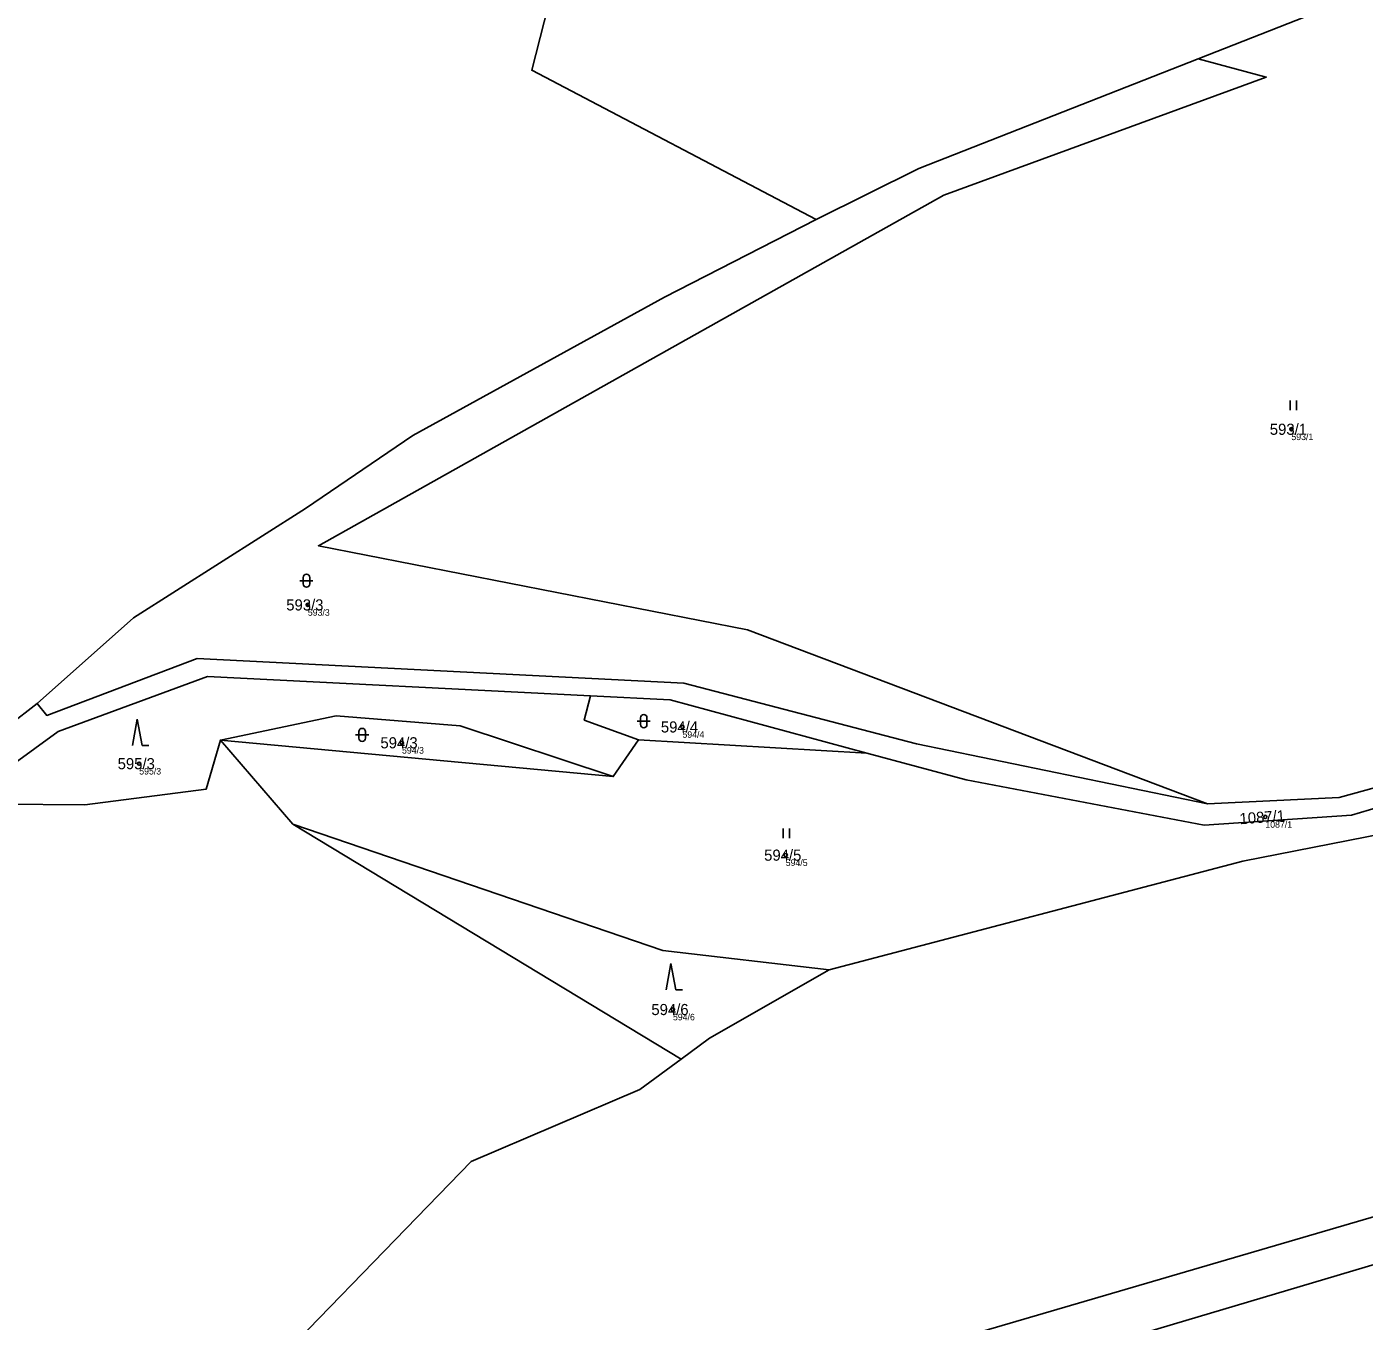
# Model space of a CAD drawing. Extents: x -554500 to -548272, y -1079733 to -1073730.
# Drawn here: x -553040.5 to -552836.2, y -1076175.5 to -1075977.7 of the extents above; entities that cross this region are included whole.
import ezdxf

# ---------------------------------------------------------------- set-up
doc = ezdxf.new("R2010")
doc.units = 0
for name, color, linetype in [('Definiční body', 7, 'Continuous'), ('Hranice parcel', 7, 'Continuous'), ('Parcelní čísla', 7, 'Continuous'), ('Polygon parcely', 7, 'Continuous'), ('Značky kultur', 7, 'Continuous')]:
    doc.layers.add(name, color=color, linetype=linetype)

msp = doc.modelspace()

# ---------------------------------------------------------------- linework, layer by layer
at = {"layer": 'Definiční body'}
for centre in [(-552847.3, -1076039.17994), (-552997.58, -1076066.01994), (-552940.34, -1076084.66994), (-552983.19, -1076087.08994), (-553023.34, -1076090.27994), (-552851.28, -1076098.41994), (-552924.56, -1076104.25994), (-552941.79, -1076127.84994)]:
    msp.add_circle(centre, 0.25, dxfattribs=at)
at = {"layer": 'Hranice parcel'}
for p, q in [((-552861.56, -1075982.55), (-552838.34, -1075973.42)), ((-553010.93, -1076086.68), (-552950.9, -1076092.26)), ((-552999.87, -1076099.51), (-553010.93, -1076086.68)), ((-552950.9, -1076092.26), (-552947.08, -1076086.65)), ((-552947.08, -1076086.65), (-552912.15, -1076088.67)), ((-552940.56, -1076135.41), (-552999.87, -1076099.51))]:
    msp.add_line(p, q, dxfattribs=at)
for points in [[(-552919.92, -1076007.14), (-552963.37, -1075984.31), (-552959.56, -1075969.5), (-552981.08, -1075928.96), (-552995.11, -1075875.98), (-552991.19, -1075866.06), (-552990.49, -1075854.9), (-553000.03, -1075843.3), (-553017.31, -1075831.78), (-553046.52, -1075836.31)], [(-552861.56, -1075982.55), (-552851.15, -1075985.37), (-552900.4, -1076003.39), (-552995.96, -1076056.98), (-552930.41, -1076069.82), (-552860.14, -1076096.43)], [(-552919.92, -1076007.14), (-552904.2, -1075999.32), (-552861.56, -1075982.55)], [(-553038.93, -1076081.06), (-553024.21, -1076067.98), (-552997.92, -1076051.27), (-552981.53, -1076040.12), (-552943.09, -1076018.97), (-552919.92, -1076007.14)], [(-552860.14, -1076096.43), (-552840.02, -1076095.45), (-552790.38, -1076081.78), (-552737.59, -1076046.37)], [(-552860.14, -1076096.43), (-552904.6, -1076087.24), (-552940.15, -1076078), (-553014.48, -1076074.23), (-553037.47, -1076082.91), (-553038.93, -1076081.06)], [(-553092.46, -1076138.34), (-553084, -1076120.53), (-553035.75, -1076085.34), (-553012.89, -1076076.96), (-552954.39, -1076079.91)], [(-552954.39, -1076079.91), (-552955.35, -1076083.65), (-552947.08, -1076086.65)], [(-552912.15, -1076088.67), (-552942.21, -1076080.53), (-552954.39, -1076079.91)], [(-553087.02, -1076118.95), (-553086.61, -1076118.06), (-553038.93, -1076081.06)], [(-552950.9, -1076092.26), (-552974.31, -1076084.49), (-552993.25, -1076082.98), (-553010.93, -1076086.68)], [(-552667.84, -1076085.54), (-552749.05, -1076137.84), (-552769.43, -1076147.39), (-552924.37, -1076193.48), (-552926.61, -1076186.44), (-552774.05, -1076141.73)], [(-553010.93, -1076086.68), (-553013.09, -1076094.16), (-553031.66, -1076096.55), (-553044.42, -1076096.49), (-553081.05, -1076121.85), (-553088.83, -1076138.77), (-553092.46, -1076138.34)], [(-552912.15, -1076088.67), (-552896.99, -1076092.77), (-552860.62, -1076099.7), (-552838.1, -1076098.16), (-552833.99, -1076096.95)], [(-552999.87, -1076099.51), (-552943.33, -1076118.81), (-552917.93, -1076121.8)], [(-552830.56, -1076100.44), (-552854.71, -1076105.19), (-552917.93, -1076121.8)], [(-552917.93, -1076121.8), (-552936.23, -1076132.22), (-552940.56, -1076135.41)], [(-553057.73, -1076226.35), (-553042.86, -1076212.91), (-553010.78, -1076190.42), (-552972.64, -1076151.06), (-552946.87, -1076140.07), (-552940.56, -1076135.41)]]:
    msp.add_lwpolyline(points, dxfattribs=at)
at = {"layer": 'Polygon parcely'}
for points in [[(-553084, -1076120.53), (-553035.75, -1076085.34), (-553012.89, -1076076.96), (-552954.39, -1076079.91), (-552942.21, -1076080.53), (-552912.15, -1076088.67), (-552896.99, -1076092.77), (-552860.62, -1076099.7), (-552838.1, -1076098.16), (-552833.99, -1076096.95), (-552789.7, -1076083.85), (-552736.11, -1076047.61), (-552731.95, -1076044.8), (-552723.58, -1076025.93), (-552709.83, -1075989.85), (-552691.6, -1075939.65)], [(-553090.31, -1075971.08), (-553065.6, -1075986.4), (-553085.31, -1076015.46), (-553098.03, -1076067.52), (-553102.22, -1076124.99), (-553087.02, -1076118.95), (-553086.61, -1076118.06), (-553038.93, -1076081.06), (-553024.21, -1076067.98), (-552997.92, -1076051.27), (-552981.53, -1076040.12), (-552943.09, -1076018.97), (-552919.92, -1076007.14), (-552963.37, -1075984.31), (-552959.56, -1075969.5)], [(-552704.81, -1075969.12), (-552726.95, -1076028.08), (-552735.18, -1076044.75), (-552737.59, -1076046.37), (-552790.38, -1076081.78), (-552840.02, -1076095.45), (-552860.14, -1076096.43), (-552904.6, -1076087.24), (-552940.15, -1076078), (-553014.48, -1076074.23), (-553037.47, -1076082.91), (-553038.93, -1076081.06), (-553086.61, -1076118.06)], [(-552959.56, -1075969.5), (-552963.37, -1075984.31), (-552919.92, -1076007.14), (-552904.2, -1075999.32), (-552861.56, -1075982.55), (-552838.34, -1075973.42)], [(-552724.95, -1076176.74), (-552652.03, -1076122.91), (-552644.88, -1076117.08), (-552662.64, -1076092.68), (-552667.84, -1076085.54), (-552749.05, -1076137.84), (-552769.43, -1076147.39), (-552924.37, -1076193.48)], [(-552926.61, -1076186.44), (-552774.05, -1076141.73), (-552773.26, -1076134.88), (-552772.82, -1076131.12), (-552773.47, -1076131.35), (-552782.83, -1076126.18), (-552803.17, -1076122.39), (-552811.71, -1076119.63), (-552830.56, -1076100.44), (-552854.71, -1076105.19), (-552917.93, -1076121.8), (-552936.23, -1076132.22), (-552940.56, -1076135.41), (-552946.87, -1076140.07), (-552972.64, -1076151.06), (-553010.78, -1076190.42)]]:
    msp.add_lwpolyline(points, dxfattribs=at)
for points in [[(-552995.96, -1076056.98), (-552930.41, -1076069.82), (-552860.14, -1076096.43), (-552840.02, -1076095.45), (-552790.38, -1076081.78), (-552737.59, -1076046.37), (-552828.94, -1075969.72), (-552838.34, -1075973.42), (-552861.56, -1075982.55), (-552851.15, -1075985.37), (-552900.4, -1076003.39)], [(-552919.92, -1076007.14), (-552943.09, -1076018.97), (-552981.53, -1076040.12), (-552997.92, -1076051.27), (-553024.21, -1076067.98), (-553038.93, -1076081.06), (-553037.47, -1076082.91), (-553014.48, -1076074.23), (-552940.15, -1076078), (-552904.6, -1076087.24), (-552860.14, -1076096.43), (-552930.41, -1076069.82), (-552995.96, -1076056.98), (-552900.4, -1076003.39), (-552851.15, -1075985.37), (-552861.56, -1075982.55), (-552904.2, -1075999.32)], [(-552954.39, -1076079.91), (-553012.89, -1076076.96), (-553035.75, -1076085.34), (-553084, -1076120.53), (-553092.46, -1076138.34), (-553088.83, -1076138.77), (-553081.05, -1076121.85), (-553044.42, -1076096.49), (-553031.66, -1076096.55), (-553013.09, -1076094.16), (-553010.93, -1076086.68), (-552993.25, -1076082.98), (-552974.31, -1076084.49), (-552950.9, -1076092.26), (-552947.08, -1076086.65), (-552955.35, -1076083.65)], [(-552942.21, -1076080.53), (-552954.39, -1076079.91), (-552955.35, -1076083.65), (-552947.08, -1076086.65), (-552912.15, -1076088.67)], [(-552755.26, -1076133.09), (-552774.05, -1076141.73), (-552926.61, -1076186.44), (-552924.37, -1076193.48), (-552769.43, -1076147.39), (-552749.05, -1076137.84), (-552667.84, -1076085.54), (-552672.38, -1076079.28), (-552675.41, -1076081.49), (-552696.65, -1076096.97), (-552722.39, -1076113.31)], [(-553010.93, -1076086.68), (-552950.9, -1076092.26), (-552974.31, -1076084.49), (-552993.25, -1076082.98)], [(-553117.7, -1076189.63), (-553128.74, -1076194.83), (-553118.72, -1076200.32), (-553115.55, -1076202.05), (-553101.8, -1076190.57), (-553101.44, -1076219.6), (-553093.66, -1076247.48), (-553084.5, -1076244.94), (-553057.73, -1076226.35), (-553042.86, -1076212.91), (-553010.78, -1076190.42), (-552972.64, -1076151.06), (-552946.87, -1076140.07), (-552940.56, -1076135.41), (-552999.87, -1076099.51), (-553010.93, -1076086.68), (-553013.09, -1076094.16), (-553031.66, -1076096.55), (-553044.42, -1076096.49), (-553081.05, -1076121.85), (-553088.83, -1076138.77), (-553092.46, -1076138.34)], [(-552917.93, -1076121.8), (-552854.71, -1076105.19), (-552830.56, -1076100.44), (-552833.99, -1076096.95), (-552838.1, -1076098.16), (-552860.62, -1076099.7), (-552896.99, -1076092.77), (-552912.15, -1076088.67), (-552947.08, -1076086.65), (-552950.9, -1076092.26), (-553010.93, -1076086.68), (-552999.87, -1076099.51), (-552943.33, -1076118.81)], [(-552999.87, -1076099.51), (-552940.56, -1076135.41), (-552936.23, -1076132.22), (-552917.93, -1076121.8), (-552943.33, -1076118.81)]]:
    msp.add_lwpolyline(points, close=True, dxfattribs=at)
at = {"layer": 'Značky kultur'}
for p, q in [((-552847.501, -1076036.26), (-552847.501, -1076034.76)), ((-552846.5, -1076036.26), (-552846.5, -1076034.76)), ((-552998.291, -1076061.821), (-552998.291, -1076062.822)), ((-552997.289, -1076062.822), (-552997.289, -1076061.821)), ((-552998.791, -1076062.321), (-552996.789, -1076062.321)), ((-553023.63, -1076083.49), (-553024.38, -1076087.49)), ((-553022.88, -1076087.49), (-553023.63, -1076083.49)), ((-552947.261, -1076083.791), (-552945.259, -1076083.791)), ((-552946.761, -1076083.291), (-552946.761, -1076084.292)), ((-552945.759, -1076084.292), (-552945.759, -1076083.291)), ((-552990.281, -1076085.881), (-552988.279, -1076085.881)), ((-552989.781, -1076085.381), (-552989.781, -1076086.382)), ((-552988.779, -1076086.382), (-552988.779, -1076085.381)), ((-553022.88, -1076087.49), (-553021.884, -1076087.49)), ((-552924.961, -1076101.67), (-552924.961, -1076100.17)), ((-552923.96, -1076101.67), (-552923.96, -1076100.17)), ((-552942.1, -1076120.83), (-552942.85, -1076124.83)), ((-552941.35, -1076124.83), (-552942.1, -1076120.83)), ((-552941.35, -1076124.83), (-552940.354, -1076124.83))]:
    msp.add_line(p, q, dxfattribs=at)
for centre, start, end in [((-552997.79, -1076061.8209), 0, 180), ((-552997.79, -1076062.8209), 180, 359.9878861), ((-552946.26, -1076083.2909), 0, 180), ((-552946.26, -1076084.2909), 180, 359.9878861), ((-552989.28, -1076085.3809), 0, 180), ((-552989.28, -1076086.3809), 180, 359.9878861)]:
    msp.add_arc(centre, 0.5, start, end, dxfattribs=at)

# ---------------------------------------------------------------- texts
at = {"layer": 'Definiční body'}
for s, p in [('593/1', (-552847.3, -1076040.836)), ('593/3', (-552997.58, -1076067.676)), ('594/4', (-552940.34, -1076086.326)), ('594/3', (-552983.19, -1076088.746)), ('595/3', (-553023.34, -1076091.936)), ('1087/1', (-552851.28, -1076100.076)), ('594/5', (-552924.56, -1076105.916)), ('594/6', (-552941.79, -1076129.506))]:
    msp.add_text(s, height=0.999996, dxfattribs=at).set_placement(p)
at = {"layer": 'Parcelní čísla'}
for s, p in [('593/1', (-552850.598, -1076040.03)), ('593/3', (-553000.878, -1076066.87)), ('594/4', (-552943.638, -1076085.52)), ('594/3', (-552986.488, -1076087.94)), ('595/3', (-553026.638, -1076091.13)), ('594/5', (-552927.858, -1076105.11)), ('594/6', (-552945.088, -1076128.7))]:
    msp.add_text(s, height=1.699998, dxfattribs=at).set_placement(p)
msp.add_text('1087/1', height=1.699998, rotation=4, dxfattribs=at).set_placement((-552855.158, -1076099.543))

doc.saveas('drawing.dxf')
